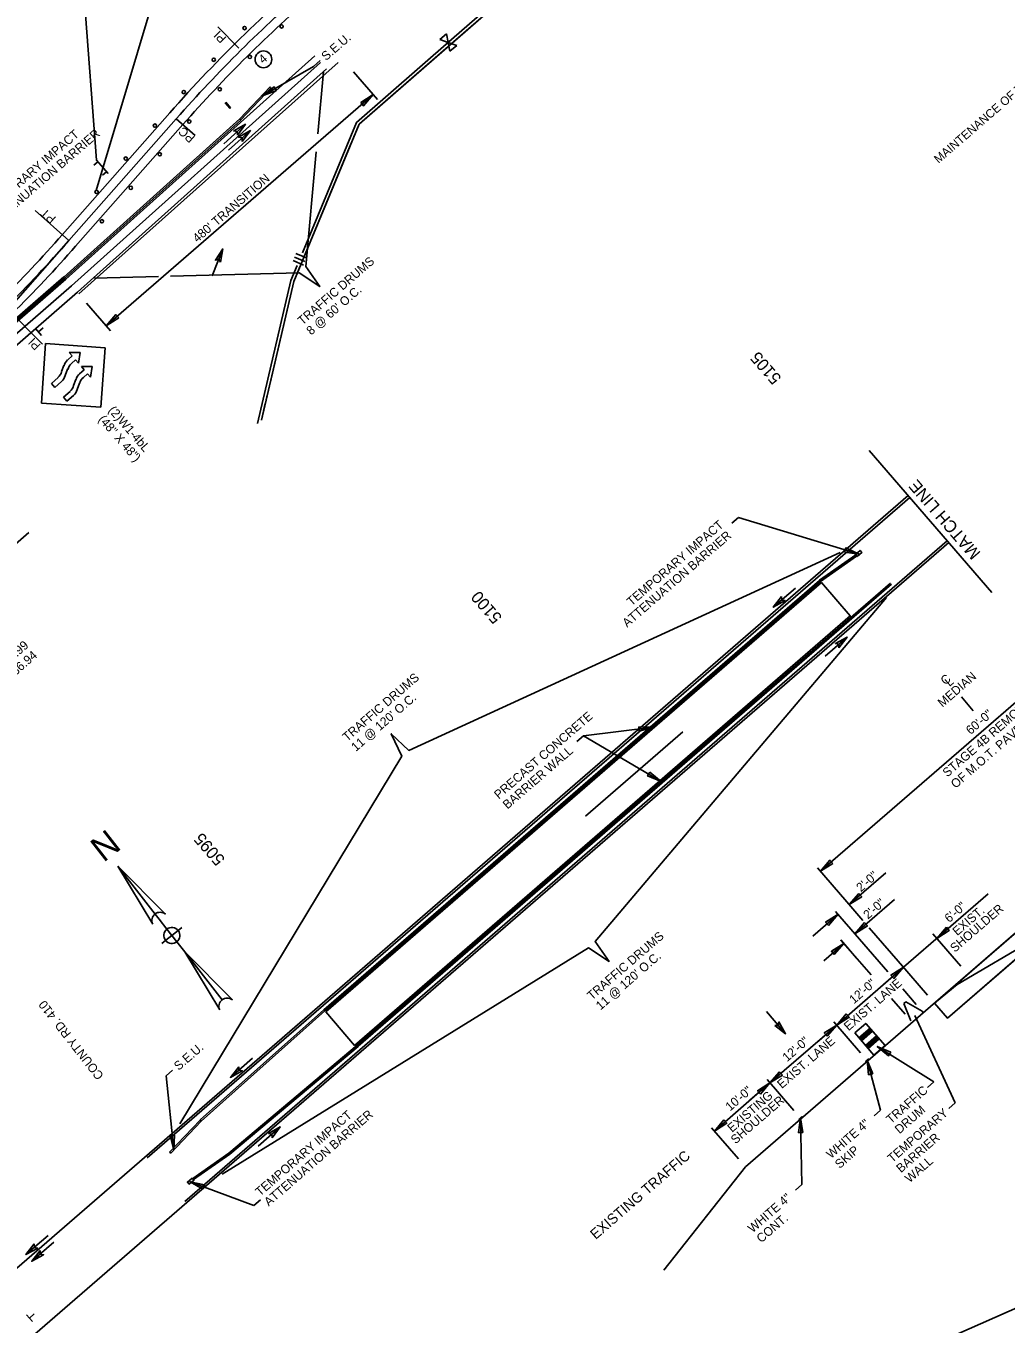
# Model space of a CAD drawing. Extents: x 259983 to 267998, y 211467 to 219827.
# Drawn here: x 265258 to 266591, y 212982 to 214746 of the extents above; entities that cross this region are included whole.
import ezdxf

# ---------------------------------------------------------------- set-up
doc = ezdxf.new("R2010")
doc.units = 0
for name, color, linetype in [('1', 7, 'Continuous'), ('CL', 7, 'Continuous'), ('Default', 7, 'Continuous'), ('DRAINAGE', 7, 'Continuous'), ('Level 1', 7, 'Continuous'), ('Level 43', 7, 'Continuous'), ('Level 58', 7, 'Continuous'), ('R-W - CofA', 7, 'Continuous'), ('R_Horz Alg Annot', 7, 'Continuous'), ('R_MOT', 7, 'Continuous'), ('R_MOT STAGE 1', 7, 'Continuous'), ('R_MOT STAGE 2', 7, 'Continuous'), ('STATIONING1', 7, 'Continuous')]:
    doc.layers.add(name, color=color, linetype=linetype)

msp = doc.modelspace()

# ---------------------------------------------------------------- linework, layer by layer
at = {"layer": '1'}
for p, q in [((265658.6, 214699), (265649.5, 214691)), ((265649.5, 214691), (265580.3, 214651)), ((266218.1, 214070.3), (266227.3, 214078.3)), ((266227.3, 214078.3), (266391.4, 214028.1)), ((266792.3, 213990.1), (266338.7, 213597.4)), ((266016.5, 213781.3), (266122.3, 213719.4)), ((266374.6, 213555.9), (266334.7, 213602)), ((266427.8, 213595.2), (266377.9, 213552.1)), ((266451.7, 213466.9), (266566.8, 213566.5)), ((266396.5, 213530.6), (266374.6, 213555.9)), ((266439.4, 213559), (266385.7, 213512.5)), ((266362.8, 213539), (266328.3, 213509.1)), ((266430.6, 213460.6), (266359.5, 213542.8)), ((266453.5, 213464.7), (266405.2, 213520.6)), ((266529.6, 213468.5), (266491.6, 213512.4)), ((266343.4, 213475.8), (266370.6, 213499.4)), ((266387.9, 213479.4), (266366.6, 213504.1)), ((266388.6, 213478.6), (266366.7, 213503.9)), ((266407.7, 213456.5), (266388.6, 213478.6)), ((266451.7, 213466.9), (266360.9, 213388.4)), ((266424.4, 213443.3), (266451.7, 213466.9)), ((266484.3, 213429.2), (266447.7, 213471.4)), ((266454, 213403), (266435.6, 213424.3)), ((266469.1, 213416.1), (266450.8, 213437.4)), ((266360.9, 213388.4), (266270.2, 213309.8)), ((266333.7, 213364.8), (266360.9, 213388.4)), ((266393.5, 213350.7), (266357, 213392.9)), ((266522.1, 213282.8), (266467, 213401.5)), ((266493.2, 213311.3), (266416, 213359.3)), ((266420.7, 213272.9), (266402.2, 213340.7)), ((265457.8, 213327), (265449, 213319.4)), ((265449, 213319.4), (265459.5, 213218.8)), ((266270.2, 213309.8), (266194.6, 213244.4)), ((266243, 213286.2), (266270.2, 213309.8)), ((266302.8, 213272.1), (266266.3, 213314.3)), ((266484.3, 213303.6), (266493.2, 213311.3)), ((266513.2, 213275.1), (266522.1, 213282.8)), ((266411.8, 213265.2), (266420.7, 213272.9)), ((266227.2, 213206.7), (266190.7, 213248.9)), ((266313.6, 213171.5), (266311.5, 213262.2)), ((265568.4, 213143.1), (265481.7, 213175.3)), ((266304.8, 213163.9), (266313.6, 213171.5)), ((265577.6, 213151.1), (265568.4, 213143.1))]:
    msp.add_line(p, q, dxfattribs=at)
for points in [[(265655.5, 214599.4), (265663.2, 214683.7)], [(265454.9, 214406), (265629.9, 214410.5), (265658, 214391.9), (265639, 214419.1), (265653.3, 214575.1)], [(265351.8, 214403.3), (265438.6, 214405.6)], [(265467.7, 213254), (265769.4, 213753.9), (265755.1, 213784.3), (265779.3, 213761.6), (266365.5, 214030.7)], [(265525.3, 213185.7), (266023.4, 213493.3), (266051.5, 213474.8), (266032.5, 213501.9), (266428.5, 213969.5)], [(266007.5, 213773.6), (266016.5, 213781.3), (266111.8, 213793)], [(265439.2, 211680.6), (266025.4, 212744.6), (266011.1, 212775.1), (266035.2, 212752.4), (267342.6, 213329.5)]]:
    msp.add_lwpolyline(points, dxfattribs=at)
for points in [[(265599, 214658.3), (265580.3, 214651), (265595.9, 214663.5)], [(265713.7, 214642.1), (265730.6, 214652.8), (265717.6, 214637.5)], [(265384.7, 214349.3), (265367.7, 214338.6), (265380.7, 214353.8)], [(266371.6, 214031), (266391.4, 214028.1), (266373.3, 214036.7)], [(266091.8, 213793.7), (266111.8, 213793), (266092.5, 213787.8)], [(266106.7, 213732), (266122.3, 213719.4), (266103.7, 213726.9)], [(266355.6, 213608.1), (266338.7, 213597.4), (266351.7, 213612.6)], [(266390.9, 213567.3), (266377.9, 213552.1), (266394.9, 213562.8)], [(266349.8, 213523.7), (266362.8, 213539), (266345.9, 213528.3)], [(266398.7, 213527.7), (266385.7, 213512.5), (266402.6, 213523.2)], [(266510, 213521.4), (266497, 213506.2), (266514, 213516.9)], [(266357.6, 213484.2), (266370.6, 213499.4), (266353.7, 213488.7)], [(266438.7, 213451.7), (266451.7, 213466.9), (266434.7, 213456.2)], [(266434.7, 213456.2), (266451.7, 213466.9), (266438.7, 213451.7)], [(266347.9, 213373.1), (266360.9, 213388.4), (266344, 213377.7)], [(266373.9, 213403.6), (266360.9, 213388.4), (266377.9, 213399)], [(266434.4, 213351.5), (266416, 213359.3), (266431.3, 213346.4)], [(266410.1, 213322.3), (266402.2, 213340.7), (266404.2, 213320.8)], [(266283.2, 213325), (266270.2, 213309.8), (266287.1, 213320.5)], [(266257.2, 213294.6), (266270.2, 213309.8), (266253.3, 213299.1)], [(266207.6, 213259.6), (266194.6, 213244.4), (266211.5, 213255)], [(266314.9, 213242.4), (266311.5, 213262.2), (266308.9, 213242.3)], [(265460.5, 213238.8), (265459.5, 213218.8), (265454.5, 213238.2)], [(265499.1, 213165.5), (265481.7, 213175.3), (265501.3, 213171.2)]]:
    msp.add_lwpolyline(points, close=True, dxfattribs=at)
at = {"layer": 'CL'}
msp.add_line((266546.7, 213815.5), (266530.5, 213834.2), dxfattribs=at)
at = {"layer": 'Default'}
for p, q in [((266493.8, 213418.3), (267204.5, 214033.5)), ((266947.4, 213811), (266236.7, 213195.7)), ((266511.6, 213397.7), (266965.2, 213790.4)), ((266524.9, 213443.6), (266649.8, 213517.3)), ((266493.8, 213418.3), (266524.9, 213443.6)), ((266455, 213419.9), (266452.3, 213417.6)), ((266461.9, 213394), (266452.3, 213417.6)), ((266477, 213407.1), (266455, 213419.9)), ((266478.6, 213405.2), (266477, 213407.1)), ((266493.8, 213418.3), (266511.6, 213397.7)), ((266236.7, 213195.7), (266125.7, 213055.3))]:
    msp.add_line(p, q, dxfattribs=at)
for points in [[(266404.4, 213342.6), (266400.5, 213339.3), (266401.4, 213338.3), (266405.2, 213341.6)], [(266313.7, 213264.1), (266309.8, 213260.7), (266310.7, 213259.7), (266314.5, 213263.1)]]:
    msp.add_lwpolyline(points, close=True, dxfattribs=at)
at = {"layer": 'DRAINAGE'}
for p, q in [((265535.5, 214634), (265528.9, 214641.5)), ((265536.6, 214635), (265530.1, 214642.5)), ((265535.5, 214634), (265536.6, 214635))]:
    msp.add_line(p, q, dxfattribs=at)
at = {"layer": 'Level 1'}
for p, q in [((265383.2, 213604.5), (265448, 213539.1)), ((265430.9, 213525.7), (265383.2, 213604.5)), ((265383.2, 213604.5), (265434.1, 213539.3)), ((265439.5, 213532.4), (265434.1, 213539.3)), ((265439.5, 213532.4), (265450.2, 213518.7)), ((265450.2, 213518.7), (265456.9, 213510.1)), ((265456.9, 213510.1), (265465.5, 213516.8)), ((265465.5, 213516.8), (265470.6, 213520.9)), ((265465.5, 213516.8), (265465.5, 213516.8)), ((265448, 213503.2), (265443.2, 213499.4)), ((265456.9, 213510.1), (265448.6, 213503.6)), ((265456.9, 213510.1), (265463.6, 213501.6)), ((265463.6, 213501.6), (265456.9, 213510.1)), ((265463.6, 213501.6), (265474.3, 213487.8)), ((265474.3, 213487.8), (265522, 213409.1)), ((265525.3, 213422.6), (265474.3, 213487.8)), ((265474.3, 213487.8), (265539.2, 213422.5))]:
    msp.add_line(p, q, dxfattribs=at)
for centre, radius, start, end in [((265441, 213530.5), 11.2, 128, 205.3196), ((265441, 213530.5), 11.2, 50.6804, 128), ((265456.9, 213510.1), 10.9, 128, 218), ((265456.9, 213510.1), 10.9, 38, 128), ((265456.9, 213510.1), 10.9, 308, 38), ((265456.9, 213510.1), 10.9, 218, 308), ((265532.1, 213413.8), 11.2, 50.6804, 128), ((265532.1, 213413.8), 11.2, 128, 205.3196)]:
    msp.add_arc(centre, radius, start, end, dxfattribs=at)
at = {"layer": 'Level 43'}
for points in [[(265556.9, 214612.6), (265527.4, 214586.1)], [(265563.6, 214604), (265534.1, 214577.5)], [(265526.1, 214443.2), (265511.5, 214406.3)], [(266274.7, 213956.2), (266304.8, 213982.2)], [(266375.1, 213915.7), (266345.1, 213889.7)], [(266291.3, 213376.6), (266265.3, 213406.6)], [(265536.6, 213317.2), (265566.7, 213343.2)], [(265604.3, 213250), (265574.3, 213224)], [(265258.5, 213076.4), (265288.6, 213102.4)], [(265266.4, 213067.4), (265296.4, 213093.3)]]:
    msp.add_lwpolyline(points, dxfattribs=at)
at = {"layer": 'Level 58'}
for points in [[(265546, 214597.8), (265556.9, 214612.6), (265541, 214603.4), (265545.8, 214602.6)], [(265552.7, 214589.2), (265563.6, 214604), (265547.7, 214594.8), (265552.5, 214594)], [(265523, 214425.1), (265526.1, 214443.2), (265516, 214427.8), (265520.6, 214429.2)], [(266285.9, 213970.8), (266274.7, 213956.2), (266290.8, 213965.1), (266286.1, 213966)], [(266363.9, 213901.1), (266375.1, 213915.7), (266359.1, 213906.7), (266363.8, 213905.9)], [(266276.6, 213387.7), (266291.3, 213376.6), (266282.3, 213392.6), (266281.4, 213387.9)], [(265547.8, 213331.8), (265536.6, 213317.2), (265552.7, 213326.2), (265548, 213327)], [(265593.1, 213235.3), (265604.3, 213250), (265588.3, 213241), (265593, 213240.1)], [(265269.7, 213091.1), (265258.5, 213076.4), (265274.6, 213085.4), (265269.9, 213086.3)], [(265277.6, 213082), (265266.4, 213067.4), (265282.5, 213076.3), (265277.7, 213077.2)]]:
    msp.add_lwpolyline(points, close=True, dxfattribs=at)
at = {"layer": 'R-W - CofA'}
for p, q in [((265821.1, 214727.6), (265830.3, 214735.6)), ((265830.3, 214735.6), (265832.6, 214723.6)), ((265832.6, 214723.6), (265821.1, 214727.6)), ((265835, 214711.6), (265832.6, 214723.6)), ((265832.6, 214723.6), (265844.2, 214719.6)), ((265844.2, 214719.6), (265835, 214711.6)), ((265623.6, 214432), (265637.9, 214426)), ((265625.6, 214436.7), (265639.9, 214430.8)), ((265621.6, 214427.2), (265635.9, 214421.2)), ((265578.7, 214210.5), (265622.7, 214398.8))]:
    msp.add_line(p, q, dxfattribs=at)
for points in [[(265622.7, 214398.8), (265711.4, 214612.4), (266239.1, 215072.3), (266415.9, 215240.2)], [(265837.2, 214727.6), (266105.3, 214961.2)], [(265840, 214724.5), (265963.3, 214831.9)], [(265634.3, 214437.6), (265707.9, 214614.9), (265837.2, 214727.6)], [(265712.1, 214613), (265840, 214724.5)], [(265707.3, 214602.6), (265709.7, 214608.4)], [(265702.9, 214591.9), (265705.3, 214597.7)], [(265638.1, 214436), (265700.8, 214587)], [(265573.4, 214205.9), (265618.7, 214400.1), (265627.2, 214420.4)], [(265590.4, 214260.6), (265622.7, 214398.8), (265631, 214418.8)], [(265587.8, 214249.3), (265589.2, 214255.5)], [(265585.1, 214238.1), (265586.6, 214244.2)], [(265578.7, 214210.5), (265583.9, 214233)]]:
    msp.add_lwpolyline(points, dxfattribs=at)
at = {"layer": 'R_MOT'}
for p, q in [((265356.4, 214561.5), (265350.8, 214556.7)), ((265354.4, 214563.8), (265370.2, 214545.4)), ((265368.1, 214547.9), (265362.5, 214543.1)), ((265279.5, 214325.6), (265271.5, 214334.9)), ((265275.5, 214330.2), (265282, 214335.8)), ((265279.4, 214233.7), (265285.1, 214314.4)), ((265366, 214308.7), (265285.2, 214314.5)), ((265360.1, 214227.9), (265366, 214308.7)), ((265321.3, 214297.7), (265315.2, 214292.4)), ((265332, 214302.3), (265317.4, 214302.2)), ((265321.3, 214297.7), (265317.4, 214302.2)), ((265326, 214292.3), (265320.2, 214287.4)), ((265329.9, 214287.8), (265326, 214292.3)), ((265329.9, 214287.8), (265332, 214302.3)), ((265310.2, 214284.5), (265307, 214276.3)), ((265315.1, 214279.5), (265311.6, 214270.9)), ((265337.6, 214278.9), (265331.5, 214273.5)), ((265337.6, 214278.9), (265333.8, 214283.4)), ((265348.4, 214283.4), (265333.8, 214283.4)), ((265342.3, 214273.5), (265336.6, 214268.5)), ((265346.2, 214269), (265342.3, 214273.5)), ((265346.2, 214269), (265348.4, 214283.4)), ((265302.1, 214268.3), (265293, 214260.4)), ((265297.6, 214255), (265293, 214260.4)), ((265306.7, 214262.9), (265297.6, 214255)), ((265326.5, 214265.6), (265323.3, 214257.4)), ((265331.4, 214260.7), (265327.9, 214252)), ((265318.4, 214249.4), (265309.3, 214241.6)), ((265313.9, 214236.2), (265309.3, 214241.6)), ((265323.1, 214244.1), (265313.9, 214236.2)), ((265279.4, 214233.7), (265360.1, 214227.9)), ((266391, 213371.2), (266406.2, 213384.2)), ((266391.5, 213370.6), (266406.6, 213383.7)), ((266392, 213370), (266407.1, 213383.1)), ((266392.4, 213369.5), (266407.5, 213382.6)), ((266393, 213368.9), (266408.1, 213382)), ((266393.6, 213368.2), (266408.7, 213381.3)), ((266394.2, 213367.5), (266409.3, 213380.6)), ((266394.6, 213367.1), (266409.7, 213380.2)), ((266400, 213360.8), (266415.1, 213373.9)), ((266400.5, 213360.2), (266415.6, 213373.3)), ((266401, 213359.7), (266416.1, 213372.8)), ((266401.4, 213359.2), (266416.5, 213372.3)), ((266401.9, 213358.6), (266417, 213371.7)), ((266402.6, 213357.8), (266417.7, 213370.9)), ((266403.2, 213357.1), (266418.3, 213370.2)), ((266403.5, 213356.7), (266418.6, 213369.8)), ((265267.2, 212985.6), (265259.2, 212994.8)), ((265263.2, 212990.2), (265269.7, 212995.8))]:
    msp.add_line(p, q, dxfattribs=at)
msp.add_lwpolyline([(266385.4, 213377.6), (266400.5, 213390.7), (266426.7, 213360.5), (266411.6, 213347.4)], close=True, dxfattribs=at)
for centre, major_axis in [((265326.5, 214278.7), (-11.6, 13.4)), ((265290.7, 214282), (11.6, -13.4)), ((265295.4, 214276.6), (11.6, -13.4)), ((265331.6, 214273.7), (-11.6, 13.4)), ((265342.8, 214259.9), (-11.6, 13.4)), ((265307, 214263.1), (11.6, -13.4)), ((265347.9, 214254.9), (-11.6, 13.4)), ((265311.7, 214257.7), (11.6, -13.4))]:
    msp.add_ellipse(centre, major_axis=major_axis, ratio=0.9, start_param=6.26006, end_param=6.849246, dxfattribs=at)
at = {"layer": 'R_MOT STAGE 1'}
for p, q in [((265334, 214834.2), (265354.4, 214563.8)), ((265519.4, 214744.7), (265547.8, 214716.1)), ((265312.6, 214401.9), (265651.1, 214705.6)), ((265320.6, 214393), (265659.1, 214696.6)), ((265330.4, 214382), (265682.8, 214696.6)), ((265328.6, 214384.1), (265667.1, 214687.7)), ((265590.5, 214663.2), (265549.3, 214619.7)), ((265592, 214661.9), (265550.8, 214618.3)), ((265590.5, 214663.2), (265592, 214661.9)), ((265308, 214462.6), (265453.9, 214627.9)), ((265309.9, 214404.9), (265549.3, 214619.7)), ((265311.2, 214403.4), (265550.6, 214618.1)), ((265317, 214454.7), (265462.9, 214620)), ((265326, 214446.7), (265471.9, 214612)), ((265462.9, 214620), (265488.7, 214597.1)), ((265549.3, 214619.7), (265550.8, 214618.3)), ((265549.3, 214619.6), (265550.6, 214618.1)), ((265317, 214454.7), (265271.1, 214495.1)), ((265317, 214454.7), (265234.2, 214360.8)), ((263990.3, 213262.5), (265310, 214405)), ((263991.6, 213261), (265311.3, 214403.5)), ((265093.3, 214212.1), (265312.6, 214402)), ((265101.2, 214203), (265320.6, 214393)), ((265109, 214194), (265328.6, 214384.1)), ((265328.6, 214384.1), (265328.6, 214384.1)), ((265281, 214313.6), (265234.2, 214360.8)), ((266572, 213976.4), (266405, 214169.3)), ((264624.1, 212519.9), (266458.3, 214107.8)), ((265423.2, 213207.8), (266460.2, 214105.5)), ((264118, 213067.1), (265262.3, 214057.6)), ((264679, 212456.4), (266513.2, 214044.3)), ((265474.3, 213148.8), (266511.3, 214046.6)), ((266337.6, 213992.8), (266386.8, 214027.2)), ((266387.9, 214025.6), (266338.8, 213991.1)), ((266386.8, 214027.2), (266387.9, 214025.6)), ((265663.5, 213409.2), (266337.5, 213992.7)), ((265666.9, 213409.5), (266338.8, 213991.1)), ((265708.8, 213361.1), (266434.2, 213989.1)), ((266337.5, 213992.7), (266338.8, 213991.1)), ((266337.6, 213992.8), (266338.8, 213991.1)), ((266435.5, 213987.6), (265710.1, 213359.6)), ((265664.8, 213407.7), (266099.5, 213784)), ((266019.5, 213672.4), (266151.7, 213786.9)), ((265495.4, 213259.4), (265663.5, 213409.2)), ((265496.8, 213258), (265664.8, 213407.7)), ((265666.9, 213409.5), (265665.4, 213410.8)), ((265665.6, 213411), (265666.9, 213409.5)), ((265708.8, 213361), (265534.5, 213214.4)), ((265710, 213359.4), (265535.8, 213212.9)), ((265708.8, 213361.1), (265710.1, 213359.6)), ((265708.8, 213361), (265710, 213359.4)), ((265453.8, 213215.8), (265495.2, 213259.2)), ((265455.3, 213214.4), (265496.6, 213257.8)), ((265496.7, 213257.9), (265495.2, 213259.2)), ((265496.7, 213257.9), (265495.4, 213259.4)), ((265455.3, 213214.4), (265453.8, 213215.8)), ((265534.3, 213214.3), (265485.2, 213179.9)), ((265535.6, 213212.8), (265486.3, 213178.3)), ((265535.6, 213212.8), (265534.5, 213214.4)), ((265535.8, 213212.9), (265534.5, 213214.4)), ((265486.3, 213178.3), (265485.2, 213179.9))]:
    msp.add_line(p, q, dxfattribs=at)
for points in [[(266388.7, 214025), (266395, 214030.4), (266392.6, 214033.3), (266386.3, 214027.8)], [(265484.4, 213180.5), (265478.1, 213175.1), (265480.5, 213172.2), (265486.8, 213177.6)]]:
    msp.add_lwpolyline(points, close=True, dxfattribs=at)
for centre, radius in [((265606.1, 214745.5), 2.25), ((265555.8, 214743.1), 2.25), ((265581.4, 214700.7), 11.4), ((265513.9, 214700.1), 2.25), ((265562.9, 214704), 2.25), ((265473, 214656.2), 2.25), ((265522, 214660), 2.25), ((265433.9, 214610.7), 2.25), ((265480.5, 214616.2), 2.25), ((265440.4, 214571.7), 2.25), ((265394.1, 214565.9), 2.25), ((265354.6, 214520.6), 2.25), ((265401, 214526.1), 2.25), ((265361.7, 214480.6), 2.25)]:
    msp.add_circle(centre, radius, dxfattribs=at)
for centre, radius, start, end in [((266894.8, 213356.1), 1921.9, 129.7094, 138.5667), ((266894.8, 213356.1), 1909.9, 130.8833, 138.5667), ((266894.8, 213356.1), 1897.9, 130.8833, 138.5667), ((263885.1, 215718.5), 1897.9, 311.0667, 318.5667), ((263885.1, 215718.5), 1909.9, 311.0667, 318.5667), ((263885.1, 215718.5), 1921.9, 311.0667, 318.5667)]:
    msp.add_arc(centre, radius, start, end, dxfattribs=at)
at = {"layer": 'R_MOT STAGE 2'}
for p, q in [((265703.8, 214683.7), (265736.4, 214646.1)), ((265367.7, 214338.6), (265730.6, 214652.8)), ((265340.9, 214369.5), (265373.5, 214331.9))]:
    msp.add_line(p, q, dxfattribs=at)
msp.add_lwpolyline([(265353.8, 214522.7), (265438.3, 214804.1), (265598.5, 214785)], dxfattribs=at)
for points in [[(265666.1, 213406.2), (265705.4, 213360.8), (266379.4, 213944.3), (266340.1, 213989.6)], [(266493.8, 213418.3), (266511.6, 213397.7), (266965.2, 213790.4), (266947.4, 213811)]]:
    msp.add_lwpolyline(points, close=True, dxfattribs=at)

# ---------------------------------------------------------------- texts
at = {"layer": '1'}
for s, height, rotation, p in [('S.E.U.', 12, 40.8733, (265666.5, 214698.2)), ('4', 12, 40.8733, (265581.1, 214694.1)), ('TEMPORARY IMPACT', 12, 40.8733, (265205.7, 214487.9)), ('ATTENUATION BARRIER', 12, 40.8733, (265217.4, 214474.3)), ("480' TRANSITION", 12, 40.8733, (265491.6, 214451.1)), ('TRAFFIC DRUMS', 12, 40.8921, (265634.4, 214338.9)), ("8 @ 60' O.C.", 12, 40.8921, (265646.2, 214325.3)), ('ATTENUATION BARRIER', 12, 40.8933, (266075.9, 213928.2)), ('TEMPORARY IMPACT', 12, 40.8933, (266082, 213957.2)), ('TRAFFIC DRUMS', 12, 40.9073, (265695.3, 213773.1)), ('MEDIAN', 12, 40.8733, (266504.7, 213819.6)), ('C', 12, 40.8733, (266508.5, 213849.7)), ('L', 12, 40.8733, (266514.3, 213847.7)), ("11 @ 120' O.C.", 12, 40.9073, (265707.1, 213759.5)), ('STAGE 4B REMOVAL', 12, 40.8833, (266511.3, 213724.7)), ('PRECAST CONCRETE', 12, 40.8833, (265901.4, 213694.8)), ('OF M.O.T. PAVEMENT', 12, 40.8833, (266522.5, 213709.3)), ('60\'-0"', 12, 40.8833, (266543, 213782.4)), ('BARRIER WALL', 12, 40.8833, (265913.2, 213681.2)), ('2\'-0"', 12, 40.8933, (266393.9, 213568.7)), ('2\'-0"', 12, 40.8933, (266403.5, 213531.6)), ('6\'-0"', 12, 40.8833, (266513.9, 213526.9)), ('SHOULDER', 12, 40.8833, (266521.6, 213486.5)), ('EXIST.', 12, 40.8833, (266524.8, 213509.1)), ('TRAFFIC DRUMS', 12, 40.9261, (266028, 213421.7)), ("11 @ 120' O.C.", 12, 40.9261, (266039.8, 213408.1)), ('EXIST. LANE', 12, 40.8833, (266377, 213379.9)), ('12\'-0"', 12, 40.8833, (266384.3, 213416.5)), ('COUNTY RD. 410', 12, 127.9922, (265364.9, 213319.8)), ('EXIST. LANE', 12, 40.8833, (266286.3, 213301.4)), ('12\'-0"', 12, 40.8833, (266293.5, 213337.9)), ('S.E.U.', 12, 40.8733, (265466.1, 213326)), ('10\'-0"', 12, 40.8833, (266216, 213270.8)), ('TRAFFIC', 12, 40.8833, (266434.6, 213253.6)), ('EXISTING', 12, 40.8833, (266218.6, 213241.9)), ('SHOULDER', 12, 40.8833, (266223.3, 213226)), ('TEMPORARY IMPACT', 12, 40.8733, (265576.8, 213155.1)), ('ATTENUATION BARRIER', 12, 40.8733, (265588.6, 213141.5)), ('TEMPORARY', 12, 40.8833, (266436.5, 213200.6)), ('DRUM', 12, 40.8833, (266446.3, 213239.9)), ('WHITE 4"', 12, 40.8833, (266353.1, 213206.2)), ('BARRIER', 12, 40.8833, (266448.3, 213187)), ('EXISTING TRAFFIC', 14, 40.8733, (266033.2, 213096.3)), ('SKIP', 12, 40.8833, (266364.9, 213192.6)), ('WALL', 12, 40.8833, (266460.1, 213173.3)), ('WHITE 4"', 12, 40.8833, (266246.5, 213105.3)), ('CONT.', 12, 40.8833, (266258.3, 213091.7))]:
    msp.add_text(s, height=height, rotation=rotation, dxfattribs=at).set_placement(p)
at = {"layer": 'Level 1'}
for s, height, rotation, p in [('MAINTENANCE OF TRAFFIC', 11.7, 40.8733, (266499.4, 214558.7)), ('N', 34.2, 38, (265363.9, 213608.6))]:
    msp.add_text(s, height=height, rotation=rotation, dxfattribs=at).set_placement(p)
at = {"layer": 'R_Horz Alg Annot'}
for s, p in [('   = 5120+31.99', (265178.1, 213829.1)), ('   = 5122+36.94', (265189.9, 213815.5))]:
    msp.add_text(s, height=12, rotation=40.9193, dxfattribs=at).set_placement(p)
at = {"layer": 'R_MOT'}
for s, p in [('(2)W1-4bL', (265369.7, 214223.4)), ('(48" X 48")', (265356.1, 214211))]:
    msp.add_text(s, height=12, rotation=310.8833, dxfattribs=at).set_placement(p)
at = {"layer": 'R_MOT STAGE 1'}
for s, rotation, p in [('PI', 134.725, (265531.8, 214730)), ('PC', 138.5667, (265489.2, 214595.2)), ('PT', 138.5667, (265300.2, 214485.5)), ('PI', 134.8167, (265279.6, 214312.7))]:
    msp.add_text(s, height=12, rotation=rotation, dxfattribs=at).set_placement(p)
at = {"layer": 'STATIONING1'}
for s, p in [('5105', (266286.7, 214267.9)), ('MATCH LINE', (266557.6, 214030)), ('5100', (265906.9, 213942.7)), ('5095', (265530.1, 213614))]:
    msp.add_text(s, height=16.5, rotation=130.8833, dxfattribs=at).set_placement(p)

doc.saveas('drawing.dxf')
